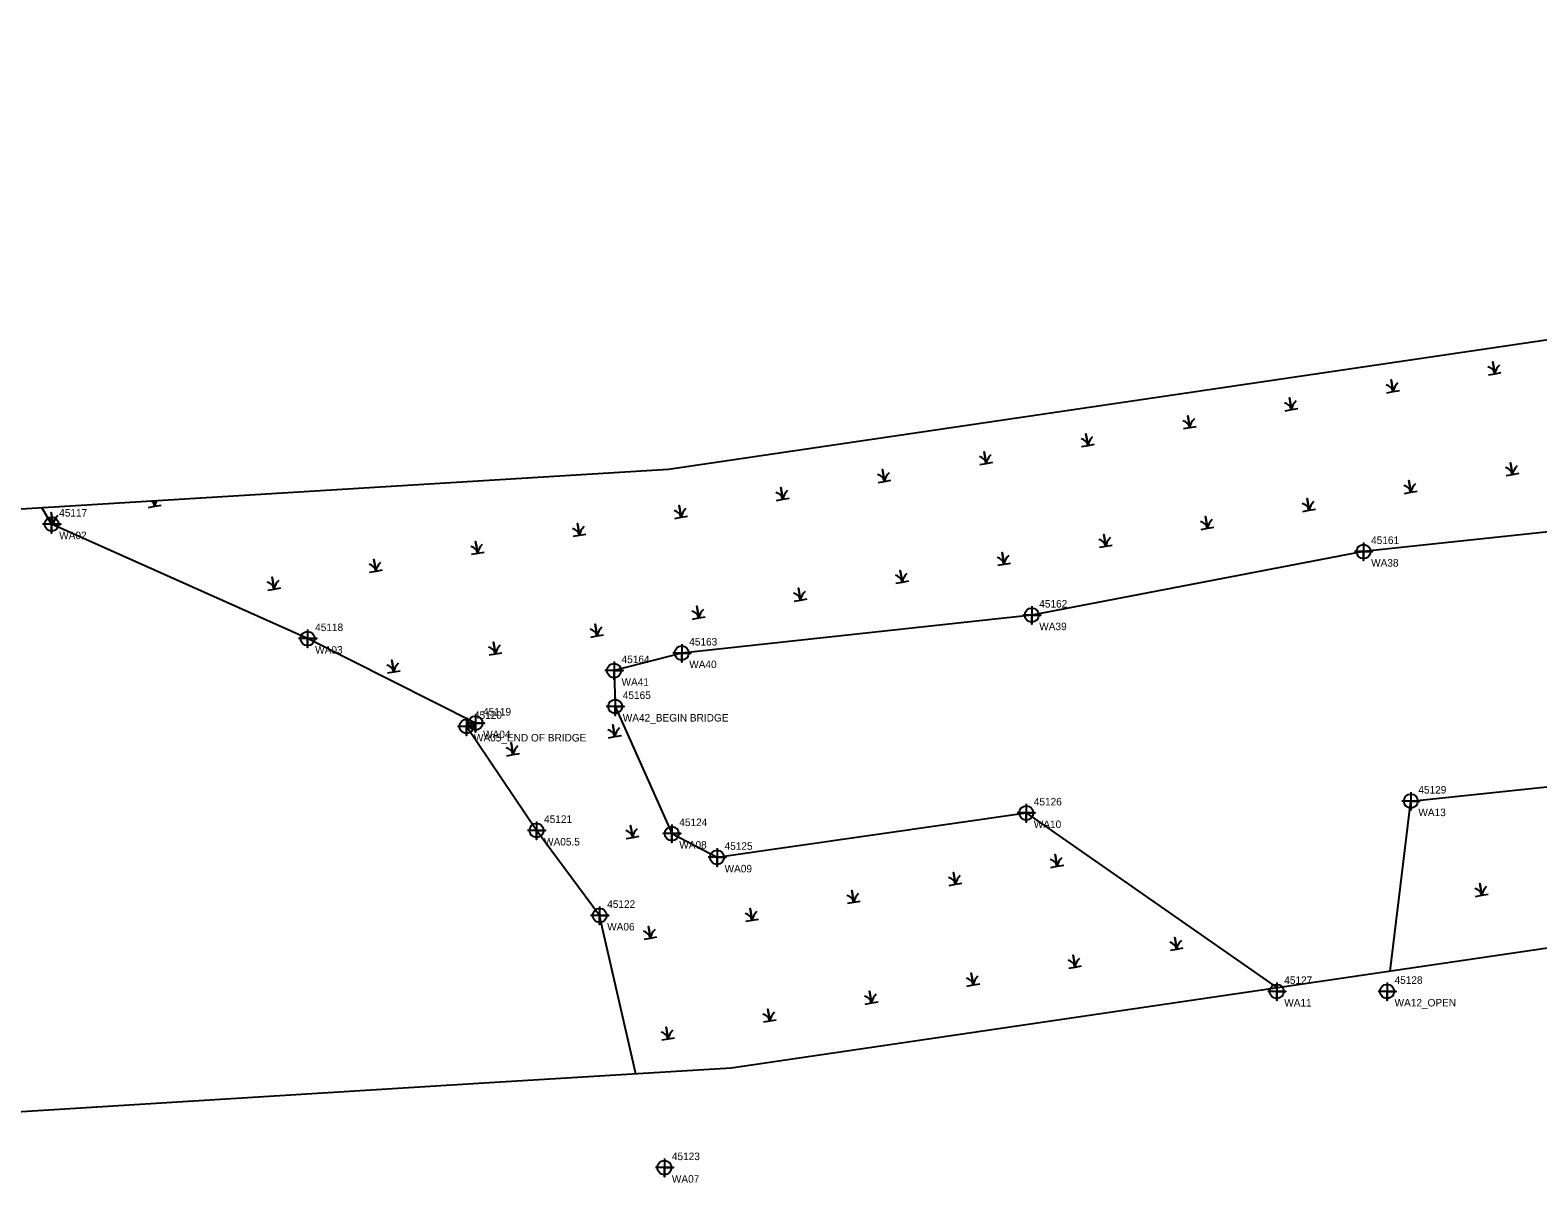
# Model space of a CAD drawing. Extents: x 2111078 to 2112659, y 581517 to 581899.
# Drawn here: x 2111368 to 2111868, y 581517 to 581899 of the extents above; entities that cross this region are included whole.
import ezdxf

# ---------------------------------------------------------------- set-up
doc = ezdxf.new("R2010")
doc.units = 0
for name, color, linetype in [('Default', 7, 'Continuous'), ('Exist Environmental Wetland Boundary', 7, 'Continuous'), ('Exist Environmental Wetland Boundary Cogo Comment', 7, 'Continuous'), ('Exist Environmental Wetland Boundary Cogo Number', 7, 'Continuous'), ('Exist Environmental Wetland Boundary Cogo Point CELL', 7, 'Continuous'), ('Exist Hydro Swamp or Marsh', 7, 'Continuous')]:
    doc.layers.add(name, color=color, linetype=linetype)

msp = doc.modelspace()

# ---------------------------------------------------------------- linework, layer by layer
at = {"layer": 'Default'}
msp.add_lwpolyline([(2111089.87, 581523.16), (2111077.52, 581722.78), (2111579.66, 581753.48), (2112568.99, 581899.18), (2112598.13, 581701.32), (2111600.4, 581554.74), (2111516.52, 581549.55)], close=True, dxfattribs=at)
at = {"layer": 'Exist Environmental Wetland Boundary'}
for points in [[(2111819.27, 581586.89), (2111826.15, 581643.33), (2111877.59, 581648.73), (2111956.11, 581679.5), (2112056.05, 581695.32), (2112056.3, 581710.43), (2112052.08, 581731.48), (2112043.26, 581752.76), (2111928.23, 581738.62), (2111810.46, 581726.15), (2111700.26, 581705.05), (2111584.01, 581692.46), (2111561.53, 581686.62), (2111561.94, 581674.72), (2111580.7, 581632.54), (2111595.75, 581624.66), (2111698.44, 581639.38), (2111781.79, 581581.39)], [(2111568.75, 581552.78), (2111568.75, 581552.78), (2111556.76, 581605.38), (2111535.8, 581633.58), (2111512.51, 581668.11), (2111515.55, 581669.22), (2111459.78, 581697.25), (2111374.77, 581735.25), (2111371.48, 581740.75)]]:
    msp.add_lwpolyline(points, dxfattribs=at)
at = {"layer": 'Exist Environmental Wetland Boundary Cogo Point CELL'}
for points in [[(2111374.77, 581738.25), (2111374.77, 581732.25), (2111374.77, 581735.25), (2111377.77, 581735.25), (2111371.77, 581735.25)], [(2111810.46, 581729.15), (2111810.46, 581723.15), (2111810.46, 581726.15), (2111813.46, 581726.15), (2111807.46, 581726.15)], [(2111700.25, 581708.05), (2111700.25, 581702.05), (2111700.25, 581705.05), (2111703.25, 581705.05), (2111697.25, 581705.05)], [(2111459.78, 581700.25), (2111459.78, 581694.25), (2111459.78, 581697.25), (2111462.78, 581697.25), (2111456.78, 581697.25)], [(2111584.01, 581695.46), (2111584.01, 581689.46), (2111584.01, 581692.46), (2111587.01, 581692.46), (2111581.01, 581692.46)], [(2111561.53, 581689.62), (2111561.53, 581683.62), (2111561.53, 581686.62), (2111564.53, 581686.62), (2111558.53, 581686.62)], [(2111561.94, 581677.72), (2111561.94, 581671.72), (2111561.94, 581674.72), (2111564.94, 581674.72), (2111558.94, 581674.72)], [(2111512.51, 581671.11), (2111512.51, 581665.11), (2111512.51, 581668.11), (2111515.51, 581668.11), (2111509.51, 581668.11)], [(2111515.55, 581672.22), (2111515.55, 581666.22), (2111515.55, 581669.22), (2111518.55, 581669.22), (2111512.55, 581669.22)], [(2111826.15, 581646.33), (2111826.15, 581640.33), (2111826.15, 581643.33), (2111829.15, 581643.33), (2111823.15, 581643.33)], [(2111698.44, 581642.38), (2111698.44, 581636.38), (2111698.44, 581639.38), (2111701.44, 581639.38), (2111695.44, 581639.38)], [(2111535.8, 581636.58), (2111535.8, 581630.58), (2111535.8, 581633.58), (2111538.8, 581633.58), (2111532.8, 581633.58)], [(2111580.7, 581635.54), (2111580.7, 581629.54), (2111580.7, 581632.54), (2111583.7, 581632.54), (2111577.7, 581632.54)], [(2111595.75, 581627.66), (2111595.75, 581621.66), (2111595.75, 581624.66), (2111598.75, 581624.66), (2111592.75, 581624.66)], [(2111556.76, 581608.38), (2111556.76, 581602.38), (2111556.76, 581605.38), (2111559.76, 581605.38), (2111553.76, 581605.38)], [(2111781.61, 581583.15), (2111781.61, 581577.15), (2111781.61, 581580.15), (2111784.61, 581580.15), (2111778.61, 581580.15)], [(2111818.25, 581583.17), (2111818.25, 581577.17), (2111818.25, 581580.17), (2111821.25, 581580.17), (2111815.25, 581580.17)], [(2111578.25, 581524.67), (2111578.25, 581518.67), (2111578.25, 581521.67), (2111581.25, 581521.67), (2111575.25, 581521.67)]]:
    msp.add_lwpolyline(points, dxfattribs=at)
for centre in [(2111374.77, 581735.25), (2111810.46, 581726.15), (2111700.25, 581705.05), (2111459.78, 581697.25), (2111584.01, 581692.46), (2111561.53, 581686.62), (2111561.94, 581674.72), (2111512.51, 581668.11), (2111515.55, 581669.22), (2111826.15, 581643.33), (2111698.44, 581639.38), (2111535.8, 581633.58), (2111580.7, 581632.54), (2111595.75, 581624.66), (2111556.76, 581605.38), (2111781.61, 581580.15), (2111818.25, 581580.17), (2111578.25, 581521.67)]:
    msp.add_circle(centre, 2.34, dxfattribs=at)
at = {"layer": 'Exist Hydro Swamp or Marsh'}
for points in [[(2111851.95, 581784.81), (2111854.07, 581785.18), (2111853.38, 581789.07), (2111854.07, 581785.18), (2111856.18, 581785.55)], [(2111818.17, 581778.85), (2111820.29, 581779.23), (2111819.6, 581783.11), (2111820.29, 581779.23), (2111822.4, 581779.6)], [(2111784.39, 581772.9), (2111786.51, 581773.27), (2111785.82, 581777.15), (2111786.51, 581773.27), (2111788.62, 581773.64)], [(2111750.61, 581766.94), (2111752.73, 581767.31), (2111752.04, 581771.2), (2111752.73, 581767.31), (2111754.85, 581767.69)], [(2111716.83, 581760.98), (2111718.95, 581761.36), (2111718.26, 581765.24), (2111718.95, 581761.36), (2111721.07, 581761.73)], [(2111683.05, 581755.03), (2111685.17, 581755.4), (2111684.48, 581759.29), (2111685.17, 581755.4), (2111687.29, 581755.77)], [(2111857.84, 581751.38), (2111859.96, 581751.75), (2111859.28, 581755.64), (2111859.96, 581751.75), (2111862.08, 581752.13)], [(2111649.27, 581749.07), (2111651.39, 581749.44), (2111650.7, 581753.33), (2111651.39, 581749.44), (2111653.51, 581749.82)], [(2111615.49, 581743.11), (2111617.61, 581743.49), (2111616.92, 581747.37), (2111617.61, 581743.49), (2111619.73, 581743.86)], [(2111824.06, 581745.42), (2111826.18, 581745.8), (2111825.5, 581749.68), (2111826.18, 581745.8), (2111828.3, 581746.17)], [(2111406.92, 581740.81), (2111409.04, 581741.18), (2111408.71, 581743.03)], [(2111408.71, 581743.03), (2111409.04, 581741.18), (2111411.15, 581741.55)], [(2111581.71, 581737.16), (2111583.83, 581737.53), (2111583.14, 581741.42), (2111583.83, 581737.53), (2111585.95, 581737.9)], [(2111790.28, 581739.47), (2111792.4, 581739.84), (2111791.72, 581743.72), (2111792.4, 581739.84), (2111794.52, 581740.21)], [(2111374.96, 581735.17), (2111375.26, 581735.22), (2111374.57, 581739.11), (2111375.26, 581735.22), (2111377.37, 581735.6)], [(2111547.93, 581731.2), (2111550.05, 581731.57), (2111549.36, 581735.46), (2111550.05, 581731.57), (2111552.17, 581731.95)], [(2111756.5, 581733.51), (2111758.62, 581733.88), (2111757.94, 581737.77), (2111758.62, 581733.88), (2111760.74, 581734.26)], [(2111722.72, 581727.55), (2111724.84, 581727.93), (2111724.16, 581731.81), (2111724.84, 581727.93), (2111726.96, 581728.3)], [(2111514.15, 581725.25), (2111516.27, 581725.62), (2111515.58, 581729.5), (2111516.27, 581725.62), (2111518.39, 581725.99)], [(2111688.94, 581721.6), (2111691.06, 581721.97), (2111690.38, 581725.86), (2111691.06, 581721.97), (2111693.18, 581722.34)], [(2111480.37, 581719.29), (2111482.49, 581719.66), (2111481.8, 581723.55), (2111482.49, 581719.66), (2111484.61, 581720.04)], [(2111446.59, 581713.33), (2111448.71, 581713.71), (2111448.02, 581717.59), (2111448.71, 581713.71), (2111450.83, 581714.08)], [(2111655.16, 581715.64), (2111657.28, 581716.01), (2111656.6, 581719.9), (2111657.28, 581716.01), (2111659.4, 581716.39)], [(2111621.39, 581709.68), (2111623.5, 581710.06), (2111622.82, 581713.94), (2111623.5, 581710.06), (2111625.62, 581710.43)], [(2111587.61, 581703.73), (2111589.72, 581704.1), (2111589.04, 581707.99), (2111589.72, 581704.1), (2111591.84, 581704.48)], [(2111553.83, 581697.77), (2111555.94, 581698.15), (2111555.26, 581702.03), (2111555.94, 581698.15), (2111558.06, 581698.52)], [(2111520.05, 581691.82), (2111522.16, 581692.19), (2111521.48, 581696.07), (2111522.16, 581692.19), (2111524.28, 581692.56)], [(2111486.27, 581685.86), (2111488.38, 581686.23), (2111487.7, 581690.12), (2111488.38, 581686.23), (2111490.5, 581686.61)], [(2111559.72, 581664.34), (2111561.84, 581664.72), (2111561.15, 581668.6), (2111561.84, 581664.72), (2111563.96, 581665.09)], [(2111525.94, 581658.39), (2111528.06, 581658.76), (2111527.37, 581662.65), (2111528.06, 581658.76), (2111530.18, 581659.13)], [(2111565.61, 581630.91), (2111567.73, 581631.29), (2111567.05, 581635.17), (2111567.73, 581631.29), (2111569.85, 581631.66)], [(2111706.63, 581621.31), (2111708.75, 581621.68), (2111708.06, 581625.57), (2111708.75, 581621.68), (2111710.86, 581622.06)], [(2111672.85, 581615.35), (2111674.97, 581615.73), (2111674.28, 581619.61), (2111674.97, 581615.73), (2111677.08, 581616.1)], [(2111847.64, 581611.7), (2111849.76, 581612.08), (2111849.07, 581615.96), (2111849.76, 581612.08), (2111851.88, 581612.45)], [(2111639.07, 581609.4), (2111641.19, 581609.77), (2111640.5, 581613.65), (2111641.19, 581609.77), (2111643.3, 581610.14)], [(2111605.29, 581603.44), (2111607.41, 581603.81), (2111606.72, 581607.7), (2111607.41, 581603.81), (2111609.52, 581604.19)], [(2111571.51, 581597.48), (2111573.63, 581597.86), (2111572.94, 581601.74), (2111573.63, 581597.86), (2111575.74, 581598.23)], [(2111746.3, 581593.84), (2111748.42, 581594.21), (2111747.74, 581598.09), (2111748.42, 581594.21), (2111750.54, 581594.58)], [(2111712.52, 581587.88), (2111714.64, 581588.25), (2111713.96, 581592.14), (2111714.64, 581588.25), (2111716.76, 581588.63)], [(2111678.74, 581581.92), (2111680.86, 581582.3), (2111680.18, 581586.18), (2111680.86, 581582.3), (2111682.98, 581582.67)], [(2111644.96, 581575.97), (2111647.08, 581576.34), (2111646.4, 581580.23), (2111647.08, 581576.34), (2111649.2, 581576.71)], [(2111611.18, 581570.01), (2111613.3, 581570.38), (2111612.62, 581574.27), (2111613.3, 581570.38), (2111615.42, 581570.76)], [(2111577.4, 581564.05), (2111579.52, 581564.43), (2111578.84, 581568.31), (2111579.52, 581564.43), (2111581.64, 581564.8)]]:
    msp.add_lwpolyline(points, dxfattribs=at)
for centre, radius, start, end in [((2111851.08, 581784.43), 3.07, 14.1403, 77.535), ((2111858.82, 581784.48), 4.81, 132.1274, 171.6222), ((2111817.31, 581778.47), 3.07, 14.1403, 77.535), ((2111825.04, 581778.52), 4.81, 132.1274, 171.6222), ((2111783.53, 581772.52), 3.07, 14.1403, 77.535), ((2111791.26, 581772.57), 4.81, 132.1274, 171.6222), ((2111749.75, 581766.56), 3.07, 14.1403, 77.535), ((2111757.48, 581766.61), 4.81, 132.1274, 171.6222), ((2111715.97, 581760.61), 3.07, 14.1403, 77.535), ((2111723.7, 581760.66), 4.81, 132.1274, 171.6222), ((2111682.19, 581754.65), 3.07, 14.1403, 77.535), ((2111689.92, 581754.7), 4.81, 132.1274, 171.6222), ((2111648.41, 581748.69), 3.07, 14.1403, 77.535), ((2111656.14, 581748.74), 4.81, 132.1274, 171.6222), ((2111856.98, 581751), 3.07, 14.1403, 77.535), ((2111864.72, 581751.05), 4.81, 132.1274, 171.6222), ((2111614.63, 581742.74), 3.07, 14.1403, 77.535), ((2111622.36, 581742.79), 4.81, 132.1274, 171.6222), ((2111823.2, 581745.04), 3.07, 14.1403, 77.535), ((2111830.94, 581745.1), 4.81, 132.1274, 171.6222), ((2111406.05, 581740.43), 3.07, 14.1403, 55.8167), ((2111413.79, 581740.48), 4.81, 147.0578, 171.6222), ((2111789.42, 581739.09), 3.07, 14.1403, 77.535), ((2111797.16, 581739.14), 4.81, 132.1274, 171.6222), ((2111372.27, 581734.47), 3.07, 14.1403, 65.0361), ((2111380.01, 581734.52), 4.81, 132.1274, 171.6222), ((2111580.85, 581736.78), 3.07, 14.1403, 77.535), ((2111588.58, 581736.83), 4.81, 132.1274, 171.6222), ((2111755.64, 581733.13), 3.07, 14.1403, 77.535), ((2111763.38, 581733.18), 4.81, 132.1274, 171.6222), ((2111547.07, 581730.82), 3.07, 14.1403, 77.535), ((2111554.8, 581730.87), 4.81, 132.1274, 171.6222), ((2111729.6, 581727.23), 4.81, 132.1274, 171.6222), ((2111513.29, 581724.87), 3.07, 14.1403, 77.535), ((2111521.02, 581724.92), 4.81, 132.1274, 171.6222), ((2111721.86, 581727.18), 3.07, 14.1403, 77.535), ((2111479.51, 581718.91), 3.07, 14.1403, 77.535), ((2111487.24, 581718.96), 4.81, 132.1274, 171.6222), ((2111688.08, 581721.22), 3.07, 14.1403, 77.535), ((2111695.82, 581721.27), 4.81, 132.1274, 171.6222), ((2111445.73, 581712.96), 3.07, 14.1403, 77.535), ((2111453.46, 581713.01), 4.81, 132.1274, 171.6222), ((2111654.3, 581715.26), 3.07, 14.1403, 77.535), ((2111662.04, 581715.31), 4.81, 132.1274, 171.6222), ((2111620.52, 581709.31), 3.07, 14.1403, 77.535), ((2111628.26, 581709.36), 4.81, 132.1274, 171.6222), ((2111586.74, 581703.35), 3.07, 14.1403, 77.535), ((2111594.48, 581703.4), 4.81, 132.1274, 171.6222), ((2111552.96, 581697.39), 3.07, 14.1403, 77.535), ((2111560.7, 581697.45), 4.81, 132.1274, 171.6222), ((2111519.18, 581691.44), 3.07, 14.1403, 77.535), ((2111526.92, 581691.49), 4.81, 132.1274, 171.6222), ((2111485.4, 581685.48), 3.07, 14.1403, 77.535), ((2111493.14, 581685.53), 4.81, 132.1274, 171.6222), ((2111558.86, 581663.96), 3.07, 14.1403, 77.535), ((2111566.59, 581664.02), 4.81, 132.1274, 171.6222), ((2111525.08, 581658.01), 3.07, 14.1403, 77.535), ((2111532.81, 581658.06), 4.81, 132.1274, 171.6222), ((2111564.75, 581630.54), 3.07, 14.1403, 77.535), ((2111572.49, 581630.59), 4.81, 132.1274, 171.6222), ((2111705.76, 581620.93), 3.07, 14.1403, 77.535), ((2111713.5, 581620.98), 4.81, 132.1274, 171.6222), ((2111671.98, 581614.97), 3.07, 14.1403, 77.535), ((2111679.72, 581615.03), 4.81, 132.1274, 171.6222), ((2111638.21, 581609.02), 3.07, 14.1403, 77.535), ((2111645.94, 581609.07), 4.81, 132.1274, 171.6222), ((2111846.78, 581611.33), 3.07, 14.1403, 77.535), ((2111854.51, 581611.38), 4.81, 132.1274, 171.6222), ((2111604.43, 581603.06), 3.07, 14.1403, 77.535), ((2111612.16, 581603.11), 4.81, 132.1274, 171.6222), ((2111578.38, 581597.16), 4.81, 132.1274, 171.6222), ((2111570.65, 581597.11), 3.07, 14.1403, 77.535), ((2111745.44, 581593.46), 3.07, 14.1403, 77.535), ((2111753.17, 581593.51), 4.81, 132.1274, 171.6222), ((2111711.66, 581587.5), 3.07, 14.1403, 77.535), ((2111719.39, 581587.55), 4.81, 132.1274, 171.6222), ((2111677.88, 581581.55), 3.07, 14.1403, 77.535), ((2111685.62, 581581.6), 4.81, 132.1274, 171.6222), ((2111644.1, 581575.59), 3.07, 14.1403, 77.535), ((2111651.84, 581575.64), 4.81, 132.1274, 171.6222), ((2111610.32, 581569.63), 3.07, 14.1403, 77.535), ((2111618.06, 581569.68), 4.81, 132.1274, 171.6222), ((2111576.54, 581563.68), 3.07, 14.1403, 77.535), ((2111584.28, 581563.73), 4.81, 132.1274, 171.6222)]:
    msp.add_arc(centre, radius, start, end, dxfattribs=at)

# ---------------------------------------------------------------- texts
at = {"layer": 'Exist Environmental Wetland Boundary Cogo Comment'}
for s, p in [('WA02', (2111377.27, 581730.25)), ('WA38', (2111812.96, 581721.15)), ('WA39', (2111702.75, 581700.05)), ('WA03', (2111462.28, 581692.25)), ('WA40', (2111586.51, 581687.46)), ('WA41', (2111564.03, 581681.62)), ('WA42_BEGIN BRIDGE', (2111564.44, 581669.72)), ('WA05_END OF BRIDGE', (2111515.01, 581663.11)), ('WA04', (2111518.05, 581664.22)), ('WA13', (2111828.65, 581638.33)), ('WA10', (2111700.94, 581634.38)), ('WA05.5', (2111538.3, 581628.58)), ('WA08', (2111583.2, 581627.54)), ('WA09', (2111598.25, 581619.66)), ('WA06', (2111559.26, 581600.38)), ('WA11', (2111784.11, 581575.15)), ('WA12_OPEN', (2111820.75, 581575.17)), ('WA07', (2111580.75, 581516.67))]:
    msp.add_text(s, height=2.5, dxfattribs=at).set_placement(p)
at = {"layer": 'Exist Environmental Wetland Boundary Cogo Number'}
for s, p in [('45117', (2111377.27, 581737.75)), ('45161', (2111812.96, 581728.65)), ('45162', (2111702.75, 581707.55)), ('45118', (2111462.28, 581699.75)), ('45163', (2111586.51, 581694.96)), ('45164', (2111564.03, 581689.12)), ('45165', (2111564.44, 581677.22)), ('45120', (2111515.01, 581670.61)), ('45119', (2111518.05, 581671.72)), ('45129', (2111828.65, 581645.83)), ('45126', (2111700.94, 581641.88)), ('45121', (2111538.3, 581636.08)), ('45124', (2111583.2, 581635.04)), ('45125', (2111598.25, 581627.16)), ('45122', (2111559.26, 581607.88)), ('45127', (2111784.11, 581582.65)), ('45128', (2111820.75, 581582.67)), ('45123', (2111580.75, 581524.17))]:
    msp.add_text(s, height=2.5, dxfattribs=at).set_placement(p)

doc.saveas('drawing.dxf')
